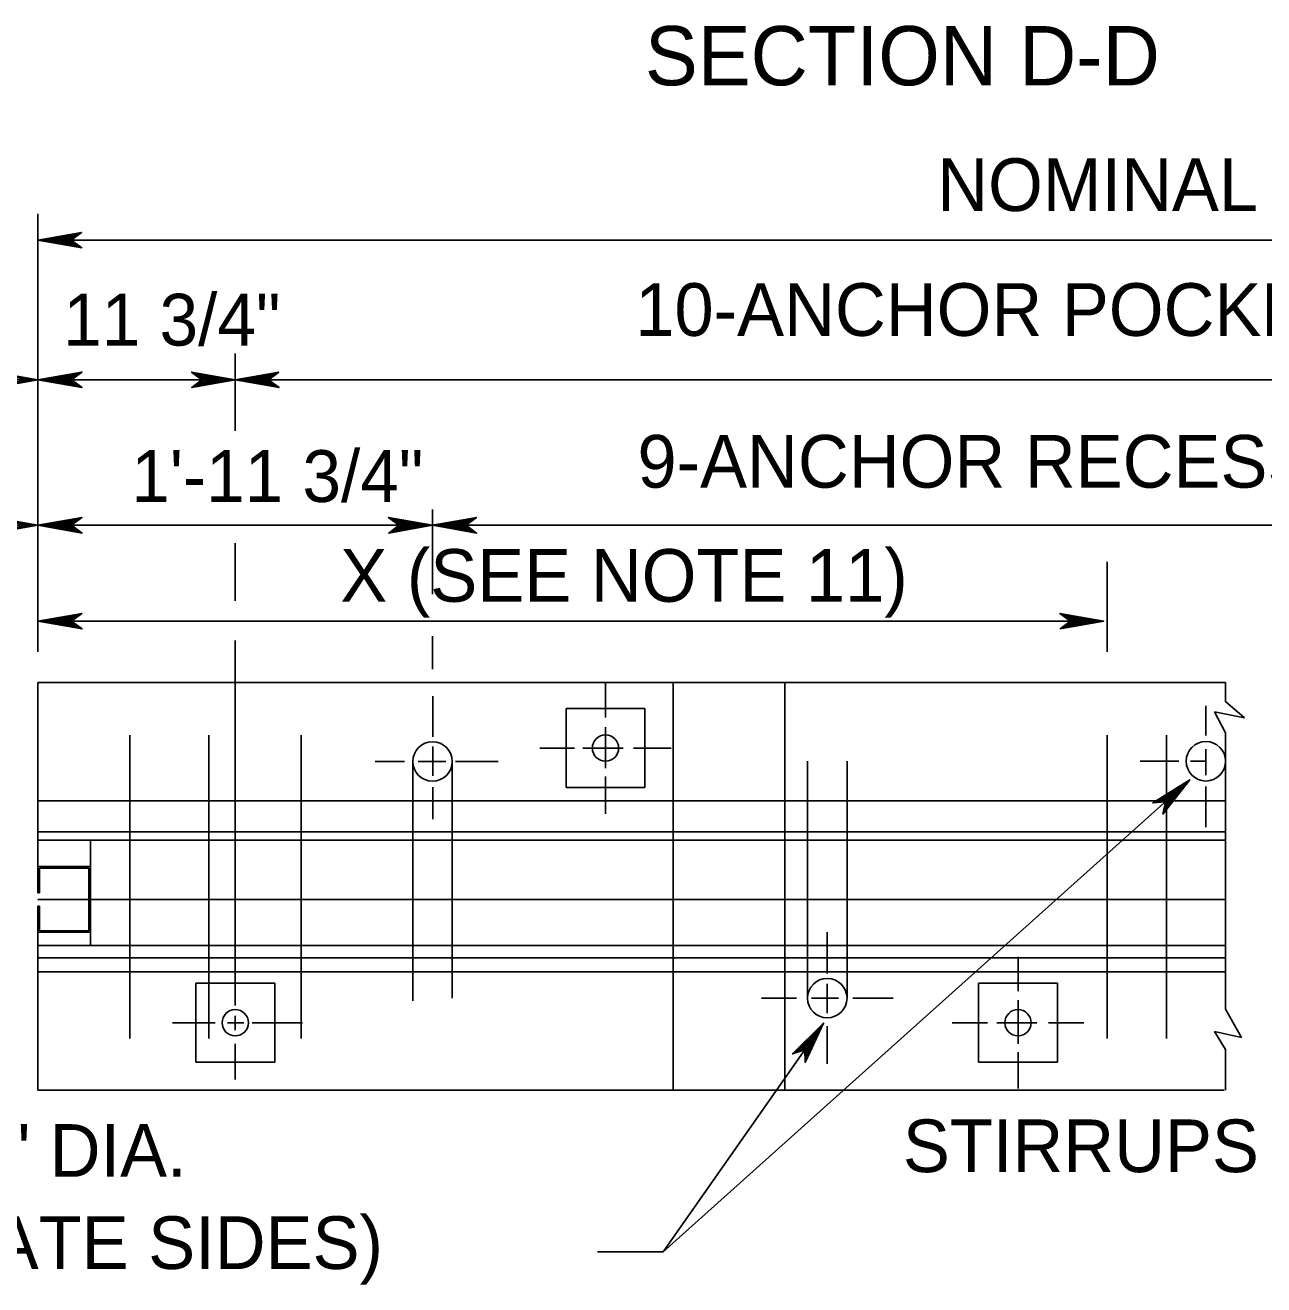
# Model space of a CAD drawing. Extents: x 499883 to 500983, y 499104 to 499764.
# Drawn here: x 500300.2 to 500394.2, y 499315.5 to 499411.2 of the extents above; entities that cross this region are included whole.
import ezdxf

# ---------------------------------------------------------------- set-up
doc = ezdxf.new("R2010")
doc.units = 0
for name, color, linetype in [('1', 7, 'Continuous'), ('24', 7, 'Continuous'), ('5', 7, 'Continuous')]:
    doc.layers.add(name, color=color, linetype=linetype)

msp = doc.modelspace()

# ---------------------------------------------------------------- linework, layer by layer
at = {"layer": '1'}
for p, q in [((500301.123, 499384.227), (500242.424, 499384.227)), ((500301.123, 499373.172), (500246.809, 499373.172)), ((500344.23, 499358.573), (500344.23, 499361.251)), ((500344.23, 499354.715), (500344.23, 499357.843)), ((500339.233, 499356.255), (500341.876, 499356.255)), ((500342.501, 499356.255), (500345.577, 499356.255)), ((500346.359, 499356.255), (500349.226, 499356.255)), ((500344.23, 499351.259), (500344.23, 499354.089)), ((500375.563, 499337.795), (500375.563, 499340.387)), ((500375.563, 499333.781), (500375.563, 499337.118)), ((500311.348, 499335.391), (500314.581, 499335.391)), ((500315.519, 499335.391), (500316.77, 499335.391)), ((500317.396, 499335.391), (500321.202, 499335.391)), ((500370.567, 499335.391), (500373.238, 499335.391)), ((500373.967, 499335.391), (500376.992, 499335.391)), ((500377.878, 499335.391), (500380.559, 499335.391)), ((500375.563, 499330.394), (500375.563, 499333.155))]:
    msp.add_line(p, q, dxfattribs=at)
at = {"layer": '24'}
for points in [[(500301.123, 499394.842), (500304.447, 499394.255), (500303.653, 499394.842), (500304.43, 499395.421), (500301.123, 499394.842), (500301.344, 499394.849), (500304.354, 499394.299), (500303.591, 499394.85), (500304.295, 499395.375), (500301.463, 499394.859), (500301.573, 499394.842), (500304.152, 499394.384), (500303.573, 499394.849), (500304.168, 499395.301), (500301.624, 499394.842), (500301.734, 499394.859), (500303.988, 499394.452), (500303.55, 499394.842), (500303.998, 499395.248), (500302.056, 499394.859), (500302.243, 499394.859), (500303.821, 499394.536), (500303.514, 499394.833), (500303.845, 499395.164), (500302.276, 499394.842), (500302.454, 499394.833), (500303.641, 499394.629), (500303.412, 499394.86), (500303.66, 499395.087), (500302.617, 499394.842), (500302.785, 499394.826), (500303.497, 499394.689), (500303.38, 499394.85), (500303.574, 499395.027), (500302.872, 499394.842), (500303.336, 499394.732), (500303.269, 499394.859), (500303.473, 499394.986), (500302.988, 499394.86), (500303.293, 499394.783), (500303.166, 499394.883), (500303.312, 499394.943), (500303.166, 499394.85), (500303.243, 499394.833)], [(500301.123, 499384.227), (500297.799, 499384.814)], [(500297.816, 499383.648), (500301.123, 499384.227), (500300.902, 499384.22), (500297.892, 499384.771)], [(500297.951, 499383.694), (500300.783, 499384.21), (500300.672, 499384.227), (500298.094, 499384.685)], [(500298.077, 499383.769), (500300.622, 499384.227), (500300.511, 499384.21), (500298.257, 499384.617)], [(500301.123, 499384.227), (500304.473, 499383.634), (500303.672, 499384.227), (500304.456, 499384.81), (500301.123, 499384.227), (500301.345, 499384.232), (500304.379, 499383.678), (500303.61, 499384.234), (500304.32, 499384.764), (500301.465, 499384.243), (500301.577, 499384.227), (500304.176, 499383.765), (500303.593, 499384.233), (500304.192, 499384.688), (500301.628, 499384.226), (500301.739, 499384.243), (500304.011, 499383.833), (500303.569, 499384.226), (500304.02, 499384.635), (500302.063, 499384.244), (500302.252, 499384.243), (500303.842, 499383.917), (500303.533, 499384.217), (500303.866, 499384.55), (500302.286, 499384.227), (500302.464, 499384.216), (500303.66, 499384.011), (500303.43, 499384.244), (500303.68, 499384.473), (500302.629, 499384.227), (500302.797, 499384.209), (500303.516, 499384.072), (500303.397, 499384.234), (500303.593, 499384.413), (500302.885, 499384.226), (500303.354, 499384.115), (500303.286, 499384.243), (500303.491, 499384.372), (500303.003, 499384.244), (500303.31, 499384.167), (500303.181, 499384.268), (500303.329, 499384.328), (500303.182, 499384.234), (500303.259, 499384.217)], [(500316.108, 499384.227), (500312.784, 499384.814), (500313.579, 499384.227), (500312.801, 499383.648), (500316.108, 499384.227), (500315.887, 499384.22), (500312.877, 499384.771), (500313.64, 499384.219), (500312.936, 499383.694), (500315.768, 499384.21), (500315.658, 499384.227), (500313.079, 499384.685), (500313.658, 499384.22), (500313.063, 499383.769), (500315.607, 499384.227), (500315.497, 499384.21), (500313.243, 499384.617), (500313.681, 499384.227), (500313.234, 499383.821), (500315.175, 499384.209), (500314.988, 499384.21), (500313.41, 499384.533), (500313.717, 499384.236), (500313.386, 499383.905), (500314.955, 499384.227), (500314.777, 499384.237), (500313.59, 499384.44), (500313.819, 499384.209), (500313.571, 499383.982), (500314.614, 499384.227), (500314.447, 499384.244), (500313.734, 499384.38), (500313.851, 499384.219), (500313.657, 499384.042), (500314.36, 499384.227), (500313.895, 499384.337), (500313.962, 499384.21), (500313.758, 499384.083), (500314.243, 499384.209), (500313.938, 499384.286), (500314.065, 499384.186), (500313.919, 499384.126), (500314.065, 499384.219), (500313.988, 499384.236)], [(500316.108, 499384.227), (500319.432, 499383.639), (500318.638, 499384.227), (500319.415, 499384.805), (500316.108, 499384.227), (500316.329, 499384.233), (500319.339, 499383.683), (500318.576, 499384.234), (500319.28, 499384.759), (500316.448, 499384.243), (500316.559, 499384.227), (500319.137, 499383.768), (500318.559, 499384.233), (500319.154, 499384.685), (500316.609, 499384.226), (500316.72, 499384.243), (500318.974, 499383.836), (500318.535, 499384.226), (500318.983, 499384.632), (500317.041, 499384.244), (500317.229, 499384.243), (500318.807, 499383.92), (500318.5, 499384.217), (500318.83, 499384.548), (500317.262, 499384.227), (500317.439, 499384.216), (500318.626, 499384.013), (500318.398, 499384.244), (500318.645, 499384.471), (500317.603, 499384.227), (500317.77, 499384.209), (500318.482, 499384.073), (500318.365, 499384.234), (500318.559, 499384.411), (500317.857, 499384.226), (500318.321, 499384.116), (500318.254, 499384.243), (500318.458, 499384.37), (500317.973, 499384.244), (500318.278, 499384.167), (500318.151, 499384.268), (500318.297, 499384.327), (500318.151, 499384.234), (500318.228, 499384.217)], [(500298.248, 499383.821), (500300.19, 499384.209), (500300.003, 499384.21)], [(500301.123, 499373.172), (500297.799, 499373.76)], [(500297.816, 499372.593), (500301.123, 499373.172), (500300.902, 499373.166), (500297.892, 499373.716)], [(500297.951, 499372.639), (500300.783, 499373.156), (500300.672, 499373.172), (500298.094, 499373.63)], [(500298.077, 499372.714), (500300.622, 499373.172), (500300.511, 499373.156), (500298.257, 499373.563)], [(500298.248, 499372.767), (500300.19, 499373.155), (500300.003, 499373.155)], [(500301.123, 499373.172), (500304.473, 499372.58), (500303.672, 499373.172), (500304.456, 499373.755), (500301.123, 499373.172), (500301.345, 499373.178), (500304.379, 499372.624), (500303.61, 499373.179), (500304.32, 499373.709), (500301.465, 499373.188), (500301.577, 499373.172), (500304.176, 499372.71), (500303.593, 499373.179), (500304.192, 499373.634), (500301.628, 499373.172), (500301.739, 499373.188), (500304.011, 499372.778), (500303.569, 499373.172), (500304.02, 499373.581), (500302.063, 499373.189), (500302.252, 499373.188), (500303.842, 499372.863), (500303.533, 499373.163), (500303.866, 499373.496), (500302.286, 499373.172), (500302.464, 499373.162), (500303.66, 499372.957), (500303.43, 499373.189), (500303.68, 499373.418), (500302.629, 499373.172), (500302.797, 499373.155), (500303.516, 499373.018), (500303.397, 499373.179), (500303.593, 499373.358), (500302.885, 499373.172), (500303.354, 499373.061), (500303.286, 499373.188), (500303.491, 499373.317), (500303.003, 499373.189), (500303.31, 499373.112), (500303.181, 499373.213), (500303.329, 499373.273), (500303.182, 499373.179), (500303.259, 499373.163)], [(500331.093, 499373.172), (500327.743, 499373.764), (500328.544, 499373.172), (500327.761, 499372.589), (500331.093, 499373.172), (500330.871, 499373.166), (500327.837, 499373.72), (500328.606, 499373.165), (500327.896, 499372.635), (500330.751, 499373.156), (500330.639, 499373.172), (500328.041, 499373.634), (500328.624, 499373.165), (500328.024, 499372.71), (500330.588, 499373.172), (500330.477, 499373.156), (500328.205, 499373.566), (500328.647, 499373.172), (500328.196, 499372.764), (500330.153, 499373.155), (500329.964, 499373.156), (500328.374, 499373.481), (500328.683, 499373.182), (500328.35, 499372.849), (500329.931, 499373.172), (500329.752, 499373.183), (500328.556, 499373.387), (500328.786, 499373.155), (500328.537, 499372.926), (500329.587, 499373.172), (500329.419, 499373.189), (500328.7, 499373.326), (500328.819, 499373.165), (500328.623, 499372.986), (500329.331, 499373.172), (500328.863, 499373.284), (500328.931, 499373.156), (500328.725, 499373.027), (500329.213, 499373.155), (500328.906, 499373.232), (500329.035, 499373.131), (500328.887, 499373.071), (500329.034, 499373.165), (500328.957, 499373.182)], [(500331.093, 499373.172), (500334.443, 499372.58), (500333.643, 499373.172), (500334.426, 499373.755), (500331.093, 499373.172), (500331.316, 499373.178), (500334.35, 499372.624), (500333.581, 499373.179), (500334.291, 499373.709), (500331.436, 499373.188), (500331.547, 499373.172), (500334.146, 499372.71), (500333.563, 499373.179), (500334.163, 499373.634), (500331.599, 499373.172), (500331.71, 499373.188), (500333.981, 499372.778), (500333.54, 499373.172), (500333.991, 499373.581), (500332.033, 499373.189), (500332.222, 499373.188), (500333.813, 499372.863), (500333.503, 499373.163), (500333.837, 499373.496), (500332.256, 499373.172), (500332.435, 499373.162), (500333.631, 499372.957), (500333.401, 499373.189), (500333.65, 499373.418), (500332.599, 499373.172), (500332.768, 499373.155), (500333.486, 499373.018), (500333.368, 499373.179), (500333.564, 499373.358), (500332.856, 499373.172), (500333.324, 499373.061), (500333.256, 499373.188), (500333.462, 499373.317), (500332.973, 499373.189), (500333.281, 499373.112), (500333.152, 499373.213), (500333.3, 499373.273), (500333.153, 499373.179), (500333.23, 499373.163)], [(500301.123, 499365.899), (500304.473, 499365.307), (500303.672, 499365.899), (500304.456, 499366.482), (500301.123, 499365.899), (500301.345, 499365.905), (500304.379, 499365.351), (500303.61, 499365.906), (500304.32, 499366.436), (500301.465, 499365.916), (500301.577, 499365.899), (500304.176, 499365.437), (500303.593, 499365.906), (500304.192, 499366.361), (500301.628, 499365.899), (500301.739, 499365.916), (500304.011, 499365.505), (500303.569, 499365.899), (500304.02, 499366.308), (500302.063, 499365.916), (500302.252, 499365.916), (500303.842, 499365.59), (500303.533, 499365.89), (500303.866, 499366.223), (500302.286, 499365.899), (500302.464, 499365.889), (500303.66, 499365.684), (500303.43, 499365.916), (500303.68, 499366.145), (500302.629, 499365.899), (500302.797, 499365.882), (500303.516, 499365.745), (500303.397, 499365.906), (500303.593, 499366.085), (500302.885, 499365.899), (500303.354, 499365.788), (500303.286, 499365.916), (500303.491, 499366.044), (500303.003, 499365.916), (500303.31, 499365.839), (500303.181, 499365.94), (500303.329, 499366), (500303.182, 499365.906), (500303.259, 499365.89)], [(500382.072, 499365.899), (500378.748, 499366.487), (500379.542, 499365.899), (500378.766, 499365.321), (500382.072, 499365.899), (500381.851, 499365.893), (500378.841, 499366.443), (500379.605, 499365.892), (500378.9, 499365.366), (500381.732, 499365.883), (500381.622, 499365.899), (500379.043, 499366.357), (500379.622, 499365.892), (500379.026, 499365.441), (500381.571, 499365.899), (500381.46, 499365.883), (500379.207, 499366.29), (500379.645, 499365.899), (500379.197, 499365.494), (500381.14, 499365.882), (500380.952, 499365.882), (500379.374, 499366.206), (500379.681, 499365.908), (500379.35, 499365.578), (500380.919, 499365.899), (500380.741, 499365.909), (500379.554, 499366.113), (500379.782, 499365.882), (500379.535, 499365.655), (500380.578, 499365.899), (500380.41, 499365.916), (500379.698, 499366.052), (500379.815, 499365.892), (500379.621, 499365.714), (500380.323, 499365.899), (500379.859, 499366.01), (500379.926, 499365.882), (500379.722, 499365.755), (500380.207, 499365.882), (500379.902, 499365.959), (500380.029, 499365.858), (500379.883, 499365.798), (500380.029, 499365.892), (500379.952, 499365.908)], [(500388.617, 499353.836), (500385.793, 499352.082), (500386.762, 499352.173), (500386.571, 499351.238), (500388.617, 499353.836), (500388.459, 499353.687), (500385.89, 499352.111), (500386.812, 499352.209), (500386.64, 499351.36), (500388.378, 499353.601), (500388.287, 499353.54), (500386.094, 499352.181), (500386.824, 499352.22), (500386.685, 499351.498), (500388.249, 499353.507), (500388.179, 499353.422), (500386.258, 499352.239), (500386.836, 499352.241), (500386.775, 499351.649), (500387.944, 499353.211), (500387.807, 499353.088), (500386.436, 499352.287), (500386.856, 499352.271), (500386.831, 499351.811), (500387.771, 499353.078), (500387.634, 499352.969), (500386.63, 499352.337), (500386.949, 499352.319), (500386.917, 499351.989), (500387.521, 499352.854), (500387.387, 499352.756), (500386.775, 499352.388), (500386.966, 499352.347), (500386.941, 499352.089), (500387.335, 499352.687), (500386.921, 499352.462), (500387.054, 499352.413), (500386.988, 499352.186), (500387.26, 499352.597), (500386.986, 499352.453), (500387.146, 499352.463), (500387.077, 499352.323), (500387.123, 499352.488), (500387.056, 499352.45)], [(500360.799, 499335.367), (500358.446, 499333.018), (500359.369, 499333.327), (500359.396, 499332.373), (500360.799, 499335.367), (500360.679, 499335.185), (500358.534, 499333.069), (500359.41, 499333.372), (500359.435, 499332.507), (500360.621, 499335.083), (500360.545, 499335.003), (500358.717, 499333.183), (500359.419, 499333.386), (500359.447, 499332.652), (500360.516, 499334.963), (500360.467, 499334.864), (500358.864, 499333.276), (500359.427, 499333.41), (500359.501, 499332.819), (500360.286, 499334.605), (500360.179, 499334.454), (500359.026, 499333.364), (500359.439, 499333.443), (500359.519, 499332.99), (500360.147, 499334.437), (500360.038, 499334.299), (500359.204, 499333.457), (500359.518, 499333.511), (500359.562, 499333.183), (500359.955, 499334.162), (500359.846, 499334.036), (500359.334, 499333.538), (500359.529, 499333.543), (500359.563, 499333.286), (500359.811, 499333.957), (500359.459, 499333.644), (500359.599, 499333.626), (500359.587, 499333.39), (500359.758, 499333.853), (500359.524, 499333.65), (500359.677, 499333.696), (500359.643, 499333.544), (500359.65, 499333.715), (500359.593, 499333.663)]]:
    msp.add_lwpolyline(points, dxfattribs=at)
at = {"layer": '5'}
for p, q in [((500301.123, 499363.562), (500301.123, 499396.841)), ((500301.123, 499394.842), (500395.609, 499394.842)), ((500316.108, 499386.225), (500316.108, 499380.348)), ((500301.123, 499384.227), (500316.108, 499384.227)), ((500316.108, 499384.227), (500395.609, 499384.227)), ((500331.093, 499367.945), (500331.093, 499374.386)), ((500331.093, 499373.172), (500301.123, 499373.172)), ((500331.093, 499373.172), (500395.793, 499373.172)), ((500316.108, 499371.817), (500316.108, 499367.441)), ((500382.34, 499363.562), (500382.34, 499370.407)), ((500382.072, 499365.899), (500301.123, 499365.899)), ((500316.108, 499364.419), (500316.108, 499336.701)), ((500331.093, 499362.236), (500331.093, 499364.755)), ((500301.123, 499361.244), (500391.333, 499361.244)), ((500301.123, 499361.244), (500301.123, 499352.251)), ((500349.368, 499361.244), (500349.368, 499330.268)), ((500357.862, 499361.244), (500357.862, 499330.268)), ((500391.333, 499361.244), (500391.333, 499359.8)), ((500331.106, 499357.118), (500331.106, 499360.203)), ((500391.296, 499359.8), (500391.333, 499359.8)), ((500391.333, 499359.8), (500392.778, 499358.545)), ((500341.232, 499359.253), (500347.227, 499359.253)), ((500341.232, 499359.253), (500341.232, 499353.258)), ((500347.227, 499359.253), (500347.227, 499353.258)), ((500389.835, 499359.472), (500389.835, 499357.198)), ((500391.333, 499357.406), (500390.498, 499359.002)), ((500390.498, 499359.002), (500392.778, 499358.545)), ((500308.111, 499357.232), (500308.111, 499334.193)), ((500314.106, 499357.232), (500314.106, 499334.193)), ((500321.101, 499357.232), (500321.101, 499334.193)), ((500382.34, 499357.232), (500382.34, 499334.193)), ((500386.837, 499357.232), (500386.837, 499334.193)), ((500391.333, 499357.406), (500391.333, 499336.428)), ((500331.106, 499354.141), (500331.106, 499356.382)), ((500389.835, 499356.174), (500389.835, 499354.189)), ((500326.73, 499355.239), (500328.971, 499355.239)), ((500329.595, 499355.239), (500329.595, 499337.055)), ((500329.996, 499355.239), (500332.109, 499355.239)), ((500332.592, 499355.183), (500332.592, 499337.262)), ((500332.845, 499355.239), (500336.089, 499355.239)), ((500359.579, 499355.249), (500359.579, 499337.262)), ((500362.576, 499355.249), (500362.576, 499337.262)), ((500387.789, 499355.249), (500384.838, 499355.249)), ((500389.835, 499355.249), (500388.653, 499355.249)), ((500331.106, 499350.843), (500331.106, 499353.276)), ((500341.232, 499353.258), (500347.227, 499353.258)), ((500389.835, 499353.324), (500389.835, 499350.252)), ((500301.123, 499352.251), (500391.333, 499352.251)), ((500301.123, 499352.251), (500301.123, 499345.256)), ((500301.123, 499349.9), (500391.333, 499349.9)), ((500301.123, 499349.253), (500391.333, 499349.253)), ((500305.12, 499349.253), (500305.12, 499341.259)), ((500301.123, 499347.254), (500305.12, 499347.254)), ((500301.248, 499347.13), (500301.248, 499345.256)), ((500301.248, 499347.13), (500304.995, 499347.13)), ((500304.995, 499347.13), (500304.995, 499342.383)), ((500301.123, 499345.256), (500301.248, 499345.256)), ((500301.123, 499344.756), (500391.333, 499344.756)), ((500301.123, 499344.257), (500301.248, 499344.257)), ((500301.123, 499344.257), (500301.123, 499339.261)), ((500301.248, 499344.257), (500301.248, 499342.383)), ((500301.248, 499342.383), (500304.995, 499342.383)), ((500301.123, 499342.258), (500305.12, 499342.258)), ((500361.077, 499339.124), (500361.077, 499342.258)), ((500301.123, 499341.26), (500391.333, 499341.26)), ((500301.123, 499341.259), (500391.333, 499341.259)), ((500301.123, 499340.332), (500391.333, 499340.332)), ((500301.123, 499339.261), (500391.333, 499339.261)), ((500301.123, 499339.261), (500301.123, 499330.268)), ((500313.11, 499338.388), (500319.106, 499338.388)), ((500313.11, 499338.388), (500313.11, 499332.393)), ((500319.106, 499338.388), (500319.106, 499332.393)), ((500361.077, 499336.114), (500361.077, 499338.355)), ((500372.565, 499338.388), (500378.561, 499338.388)), ((500372.565, 499338.388), (500372.565, 499332.393)), ((500378.561, 499338.388), (500378.561, 499332.393)), ((500356.081, 499337.262), (500358.748, 499337.262)), ((500359.869, 499337.262), (500361.918, 499337.262)), ((500363.006, 499337.262), (500366.073, 499337.262)), ((500316.108, 499335.918), (500316.108, 499334.823)), ((500391.333, 499336.428), (500392.551, 499334.262)), ((500348.622, 499317.996), (500360.799, 499335.367)), ((500361.077, 499332.266), (500361.077, 499335.122)), ((500391.333, 499333.35), (500390.498, 499334.718)), ((500390.498, 499334.718), (500392.551, 499334.262)), ((500316.108, 499333.78), (500316.108, 499331.069)), ((500391.333, 499333.35), (500391.333, 499330.268)), ((500313.11, 499332.393), (500319.106, 499332.393)), ((500372.565, 499332.393), (500378.561, 499332.393)), ((500301.123, 499330.268), (500391.228, 499330.268))]:
    msp.add_line(p, q, dxfattribs=at)
for points in [[(500301.123, 499384.227), (500304.447, 499383.639), (500303.653, 499384.227), (500304.43, 499384.805), (500301.123, 499384.227), (500301.344, 499384.233), (500304.354, 499383.683), (500303.591, 499384.234), (500304.295, 499384.759), (500301.463, 499384.243), (500301.573, 499384.227), (500304.152, 499383.768), (500303.573, 499384.233), (500304.168, 499384.685), (500301.624, 499384.226), (500301.734, 499384.243), (500303.988, 499383.836), (500303.55, 499384.226), (500303.998, 499384.632), (500302.056, 499384.244), (500302.243, 499384.243), (500303.821, 499383.92), (500303.514, 499384.217), (500303.845, 499384.548), (500302.276, 499384.227), (500302.454, 499384.216), (500303.641, 499384.013), (500303.412, 499384.244), (500303.66, 499384.471), (500302.617, 499384.227), (500302.785, 499384.209), (500303.497, 499384.073), (500303.38, 499384.234), (500303.574, 499384.411), (500302.872, 499384.226), (500303.336, 499384.116), (500303.269, 499384.243), (500303.473, 499384.37), (500302.988, 499384.244), (500303.293, 499384.167), (500303.166, 499384.268), (500303.312, 499384.327), (500303.166, 499384.234), (500303.243, 499384.217)], [(500343.626, 499317.996), (500348.622, 499317.996), (500388.617, 499353.836)]]:
    msp.add_lwpolyline(points, dxfattribs=at)
for centre, radius in [((500331.093, 499355.239), 1.499), ((500344.23, 499356.255), 0.999), ((500389.834, 499355.249), 1.499), ((500361.077, 499337.262), 1.499), ((500316.108, 499335.391), 0.999), ((500375.563, 499335.391), 0.999)]:
    msp.add_circle(centre, radius, dxfattribs=at)

# ---------------------------------------------------------------- texts
for s, height, p in [('SECTION D-D', 4.5, (500347.225, 499406.593)), ('NOMINAL LENGTH', 4, (500369.426, 499397.046)), ('10-ANCHOR POCKETS AT 2\'-0"`', 4, (500346.494, 499387.562)), ('11 3/4" ', 3.937, (500303.038, 499386.824)), ('9-ANCHOR RECESSES AT 2\'-0"`', 4, (500346.658, 499376.034)), ('1\'-11 3/4"', 3.937, (500308.206, 499374.944)), ('X (SEE NOTE 11)', 4, (500324.088, 499367.365)), ('STIRRUPS (TYPICAL)', 4, (500366.817, 499324.042)), ('1 1/4" DIA. HOLE FOR 1" DIA.', 4, (500239.652, 499323.689)), ('ANCHOR PIN (ALTERNATE SIDES)', 4, (500239.652, 499316.689))]:
    msp.add_text(s, height=height, dxfattribs=at).set_placement(p)

doc.saveas('drawing.dxf')
